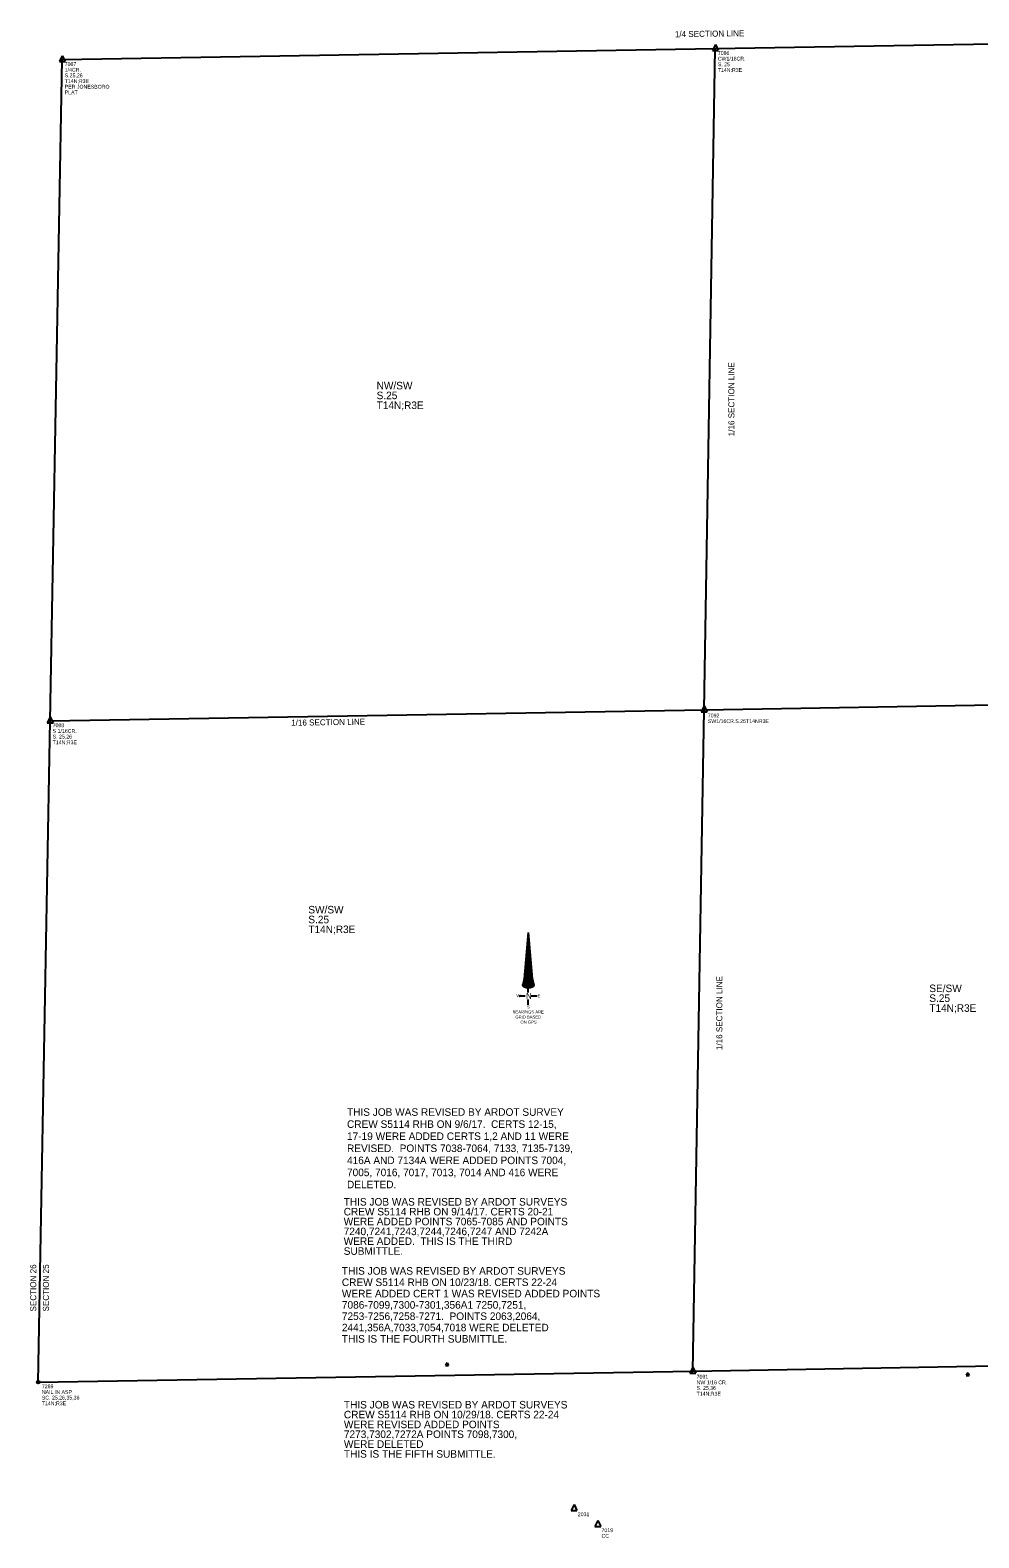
# Model space of a CAD drawing. Extents: x 1688544 to 1704497, y 535668 to 545444.
# Drawn here: x 1688544 to 1690431, y 538520 to 541517 of the extents above; entities that cross this region are included whole.
import ezdxf

# ---------------------------------------------------------------- set-up
doc = ezdxf.new("R2010")
doc.units = 0
for name, color, linetype in [('Default', 7, 'Continuous'), ('S_CAL_CORNER', 7, 'Continuous'), ('S_CAL_CORNER_ANNOT', 7, 'Continuous'), ('S_IRON_PIN', 7, 'Continuous'), ('S_IRON_PIN_ANNOT', 7, 'Continuous'), ('S_QSECTION', 7, 'Continuous'), ('S_SECONDARY_CTL', 7, 'Continuous'), ('S_SECTION', 7, 'Continuous'), ('S_SECTION_ANNOT', 7, 'Continuous'), ('S_SIXTEEN_SECTION', 7, 'Continuous'), ('S_TITLE_BLOCK', 7, 'Continuous')]:
    doc.layers.add(name, color=color, linetype=linetype)

msp = doc.modelspace()

# ---------------------------------------------------------------- linework, layer by layer
at = {"layer": 'S_CAL_CORNER'}
for p, q in [((1689906.9, 541488.4), (1689901, 541476.6)), ((1689906.9, 541488.4), (1689901, 541476.6)), ((1689906.9, 541488.4), (1689901, 541476.6)), ((1689906.9, 541488.4), (1689912.7, 541476.6)), ((1689906.9, 541488.4), (1689912.7, 541476.6)), ((1689906.9, 541488.4), (1689912.7, 541476.6)), ((1688607.6, 541466.4), (1688601.8, 541454.6)), ((1688607.6, 541466.4), (1688601.8, 541454.6)), ((1688607.6, 541466.4), (1688601.8, 541454.6)), ((1688601.8, 541454.6), (1688613.4, 541454.6)), ((1688601.8, 541454.6), (1688613.4, 541454.6)), ((1688601.8, 541454.6), (1688613.4, 541454.6)), ((1688607.6, 541466.4), (1688613.4, 541454.6)), ((1688607.6, 541466.4), (1688613.4, 541454.6)), ((1688607.6, 541466.4), (1688613.4, 541454.6)), ((1689901, 541476.6), (1689912.7, 541476.6)), ((1689901, 541476.6), (1689912.7, 541476.6)), ((1689901, 541476.6), (1689912.7, 541476.6)), ((1689884.5, 540174.1), (1689878.6, 540162.3)), ((1689884.5, 540174.1), (1689878.6, 540162.3)), ((1689884.5, 540174.1), (1689878.6, 540162.3)), ((1689878.6, 540162.3), (1689890.3, 540162.3)), ((1689878.6, 540162.3), (1689890.3, 540162.3)), ((1689878.6, 540162.3), (1689890.3, 540162.3)), ((1689884.5, 540174.1), (1689890.3, 540162.3)), ((1689884.5, 540174.1), (1689890.3, 540162.3)), ((1689884.5, 540174.1), (1689890.3, 540162.3)), ((1688583.6, 540152.1), (1688577.7, 540140.2)), ((1688583.6, 540152.1), (1688577.7, 540140.2)), ((1688583.6, 540152.1), (1688577.7, 540140.2)), ((1688577.7, 540140.2), (1688589.4, 540140.2)), ((1688577.7, 540140.2), (1688589.4, 540140.2)), ((1688577.7, 540140.2), (1688589.4, 540140.2)), ((1688583.6, 540152.1), (1688589.4, 540140.2)), ((1688583.6, 540152.1), (1688589.4, 540140.2)), ((1688583.6, 540152.1), (1688589.4, 540140.2)), ((1689862.1, 538859.8), (1689856.3, 538847.9)), ((1689862.1, 538859.8), (1689856.3, 538847.9)), ((1689862.1, 538859.8), (1689856.3, 538847.9)), ((1689856.3, 538847.9), (1689868, 538847.9)), ((1689856.3, 538847.9), (1689868, 538847.9)), ((1689856.3, 538847.9), (1689868, 538847.9)), ((1689862.1, 538859.8), (1689868, 538847.9)), ((1689862.1, 538859.8), (1689868, 538847.9)), ((1689862.1, 538859.8), (1689868, 538847.9)), ((1689625.8, 538586.2), (1689619.9, 538574.4)), ((1689619.9, 538574.4), (1689631.6, 538574.4)), ((1689625.8, 538586.2), (1689631.6, 538574.4)), ((1689673, 538554.6), (1689667.1, 538542.7)), ((1689667.1, 538542.7), (1689678.8, 538542.7)), ((1689673, 538554.6), (1689678.8, 538542.7))]:
    msp.add_line(p, q, dxfattribs=at)
at = {"layer": 'S_IRON_PIN'}
for radius in [2.91, 0.411, 0.262, 0.212, 0.0822, 0.145, 0.0581]:
    msp.add_circle((1688559.5, 538829.7), radius, dxfattribs=at)
at = {"layer": 'S_QSECTION'}
for p, q in [((1688607.5, 541458.5), (1689906.8, 541480.5)), ((1689906.8, 541480.5), (1691206, 541502.5))]:
    msp.add_line(p, q, dxfattribs=at)
at = {"layer": 'S_SECONDARY_CTL'}
for p, q in [((1689373.1, 538867.8), (1689370.1, 538862.8)), ((1689370.1, 538862.8), (1689376, 538862.8)), ((1689373.1, 538867.8), (1689376, 538862.8)), ((1690409, 538848.1), (1690406, 538843.1)), ((1690409, 538848.1), (1690406, 538843.1)), ((1690406, 538843.1), (1690412, 538843.1)), ((1690406, 538843.1), (1690412, 538843.1)), ((1690409, 538848.1), (1690412, 538843.1)), ((1690409, 538848.1), (1690412, 538843.1))]:
    msp.add_line(p, q, dxfattribs=at)
for centre, radius in [((1689373.1, 538865.1), 0.311), ((1689373.1, 538865.1), 0.183), ((1689373.1, 538865.1), 0.103), ((1690409, 538845.5), 0.311), ((1690409, 538845.5), 0.311), ((1690409, 538845.5), 0.183), ((1690409, 538845.5), 0.183), ((1690409, 538845.5), 0.103), ((1690409, 538845.5), 0.103)]:
    msp.add_circle(centre, radius, dxfattribs=at)
at = {"layer": 'S_SECTION'}
for p, q in [((1688583.5, 540144.1), (1688607.5, 541458.5)), ((1688559.5, 538829.7), (1688583.5, 540144.1)), ((1689862.1, 538851.8), (1691164.6, 538873.9)), ((1688559.5, 538829.7), (1689862.1, 538851.8))]:
    msp.add_line(p, q, dxfattribs=at)
at = {"layer": 'S_SIXTEEN_SECTION'}
for p, q in [((1689884.4, 540166.1), (1689906.8, 541480.5)), ((1688583.5, 540144.1), (1689884.4, 540166.1)), ((1689862.1, 538851.8), (1689884.4, 540166.1)), ((1689884.4, 540166.1), (1691185.3, 540188.2))]:
    msp.add_line(p, q, dxfattribs=at)
at = {"layer": 'S_TITLE_BLOCK'}
for p, q in [((1689534.7, 539723.5), (1689526.7, 539631.5)), ((1689533.6, 539711.4), (1689535.9, 539709.1)), ((1689533.8, 539713.3), (1689535.7, 539711.4)), ((1689534, 539715.3), (1689535.5, 539713.7)), ((1689534.1, 539717.2), (1689535.3, 539716.1)), ((1689534.3, 539719.2), (1689535.1, 539718.4)), ((1689534.5, 539721.2), (1689534.9, 539720.7)), ((1689534.6, 539723.1), (1689534.7, 539723)), ((1689534.7, 539723.5), (1689542.7, 539631.5)), ((1689531.1, 539682.1), (1689539, 539674.2)), ((1689531.2, 539684.1), (1689538.8, 539676.6)), ((1689531.4, 539686), (1689538.6, 539678.9)), ((1689531.6, 539688), (1689538.3, 539681.2)), ((1689531.8, 539689.9), (1689538.1, 539683.5)), ((1689531.9, 539691.9), (1689537.9, 539685.9)), ((1689532.1, 539693.8), (1689537.7, 539688.2)), ((1689532.3, 539695.8), (1689537.5, 539690.5)), ((1689532.4, 539697.7), (1689537.3, 539692.8)), ((1689532.6, 539699.7), (1689537.1, 539695.2)), ((1689532.8, 539701.6), (1689536.9, 539697.5)), ((1689532.9, 539703.6), (1689536.7, 539699.8)), ((1689533.1, 539705.5), (1689536.5, 539702.1)), ((1689533.3, 539707.5), (1689536.3, 539704.4)), ((1689533.5, 539709.4), (1689536.1, 539706.8)), ((1689528.5, 539652.8), (1689542, 539639.4)), ((1689528.7, 539654.8), (1689541.8, 539641.7)), ((1689528.9, 539656.7), (1689541.6, 539644)), ((1689529, 539658.7), (1689541.4, 539646.4)), ((1689529.2, 539660.7), (1689541.2, 539648.7)), ((1689529.4, 539662.6), (1689541, 539651)), ((1689529.6, 539664.6), (1689540.8, 539653.3)), ((1689529.7, 539666.5), (1689540.6, 539655.7)), ((1689529.9, 539668.5), (1689540.4, 539658)), ((1689530.1, 539670.4), (1689540.2, 539660.3)), ((1689530.2, 539672.4), (1689540, 539662.6)), ((1689530.4, 539674.3), (1689539.8, 539664.9)), ((1689530.6, 539676.3), (1689539.6, 539667.3)), ((1689530.7, 539678.2), (1689539.4, 539669.6)), ((1689530.9, 539680.2), (1689539.2, 539671.9)), ((1689526.7, 539631.5), (1689523.7, 539619)), ((1689524.6, 539622.8), (1689525.8, 539621.7)), ((1689525, 539624.5), (1689527.1, 539622.5)), ((1689525.4, 539626.2), (1689528.6, 539623.1)), ((1689525.8, 539628), (1689530.3, 539623.5)), ((1689526.3, 539629.7), (1689532.1, 539623.8)), ((1689526.7, 539631.4), (1689534.1, 539624)), ((1689526.8, 539633.3), (1689536.3, 539623.9)), ((1689527, 539635.3), (1689538.7, 539623.6)), ((1689527.2, 539637.2), (1689541.7, 539622.7)), ((1689527.3, 539639.2), (1689545, 539621.5)), ((1689527.5, 539641.1), (1689544.4, 539624.3)), ((1689527.7, 539643.1), (1689543.7, 539627.1)), ((1689527.9, 539645), (1689543.1, 539629.8)), ((1689528, 539647), (1689542.6, 539632.4)), ((1689528.2, 539648.9), (1689542.4, 539634.7)), ((1689528.4, 539650.9), (1689542.2, 539637.1)), ((1689542.7, 539631.5), (1689545.6, 539619)), ((1689516.7, 539597.5), (1689528.7, 539597.5)), ((1689523.8, 539619.4), (1689523.8, 539619.4)), ((1689524.2, 539621.1), (1689524.6, 539620.7)), ((1689534.7, 539604.5), (1689534.7, 539618.5)), ((1689540.7, 539597.5), (1689552.7, 539597.5)), ((1689534.7, 539579.5), (1689534.7, 539590.5))]:
    msp.add_line(p, q, dxfattribs=at)
for major_axis in [(11, 0), (9, 0), (7, 0), (5, 0), (3, 0), (1, 0)]:
    msp.add_ellipse((1689534.7, 539618.5), major_axis=major_axis, ratio=0.5, dxfattribs=at)

# ---------------------------------------------------------------- texts
at = {"layer": 'Default'}
for s, p in [('S.25', (1689233, 540783.6)), ('NW/SW', (1689233, 540803.1)), ('T14N;R3E', (1689233, 540764)), ('SW/SW', (1689097.1, 539761.4)), ('S.25', (1689097.1, 539741.8)), ('T14N;R3E', (1689097.1, 539722.3)), ('SE/SW', (1690332.5, 539605)), ('S.25', (1690332.5, 539585.4)), ('T14N;R3E', (1690332.5, 539565.8)), ('THIS JOB WAS REVISED BY ARDOT SURVEY ', (1689174.1, 539359.1)), ('CREW S5114 RHB ON 9/6/17.  CERTS 12-15,', (1689174.1, 539335.1)), ('17-19 WERE ADDED CERTS 1,2 AND 11 WERE', (1689174.1, 539311.1)), ('REVISED.  POINTS 7038-7064, 7133, 7135-7139,', (1689174.1, 539287.1)), ('416A AND 7134A WERE ADDED POINTS 7004, ', (1689174.1, 539263.1)), ('7005, 7016, 7017, 7013, 7014 AND 416 WERE', (1689174.1, 539239.1)), ('DELETED.  ', (1689174.1, 539215.1)), ('THIS JOB WAS REVISED BY ARDOT SURVEYS', (1689167.5, 539180.7)), ('CREW S5114 RHB ON 9/14/17. CERTS 20-21', (1689167.5, 539161.1)), ('WERE ADDED POINTS 7065-7085 AND POINTS', (1689167.5, 539141.5)), ('WERE ADDED.  THIS IS THE THIRD ', (1689167.5, 539102.4)), ('7240,7241,7243,7244,7246,7247 AND 7242A', (1689167.5, 539121.9)), ('SUBMITTLE.', (1689167.5, 539082.8)), ('THIS JOB WAS REVISED BY ARDOT SURVEYS', (1689163.9, 539043.3)), ('CREW S5114 RHB ON 10/23/18. CERTS 22-24', (1689163.9, 539020.8)), ('WERE ADDED CERT 1 WAS REVISED ADDED POINTS ', (1689163.9, 538998.3)), ('7086-7099,7300-7301,356A1 7250,7251,', (1689163.9, 538975.8)), ('7253-7256,7258-7271.  POINTS 2063,2064,', (1689163.9, 538953.3)), ('2441,356A,7033,7054,7018 WERE DELETED', (1689163.9, 538930.8)), ('THIS IS THE FOURTH SUBMITTLE.', (1689163.9, 538908.3)), ('THIS JOB WAS REVISED BY ARDOT SURVEYS', (1689167.9, 538777.4)), ('WERE REVISED ADDED POINTS ', (1689167.9, 538738.2)), ('CREW S5114 RHB ON 10/29/18. CERTS 22-24', (1689167.9, 538757.8)), ('7273,7302,7272A POINTS 7098,7300,', (1689167.9, 538718.7)), ('WERE DELETED', (1689167.9, 538699.1)), ('THIS IS THE FIFTH SUBMITTLE.', (1689167.9, 538679.5))]:
    msp.add_text(s, height=15, dxfattribs=at).set_placement(p)
at = {"layer": 'S_CAL_CORNER_ANNOT'}
for s, p in [('7087', (1688612.5, 541446)), ('S. 25', (1689911.8, 541445.5)), ('7086', (1689911.8, 541468)), ('CW1/16CR.', (1689911.8, 541456.7)), ('T14N;R3E', (1688612.5, 541412.2)), ('S.25,26', (1688612.5, 541423.5)), ('1/4CR.', (1688612.5, 541434.7)), ('T14N;R3E', (1689911.8, 541434.2)), ('PER JONESBORO', (1688612.5, 541401)), ('PLAT', (1688612.5, 541389.7)), ('7088', (1688588.5, 540131.6)), ('7092', (1689891.9, 540151.1)), ('SW1/16CR.S.25T14NR3E', (1689891.9, 540139.9)), ('T14N;R3E', (1688588.5, 540097.8)), ('S 1/16CR.', (1688588.5, 540120.3)), ('S. 25,26', (1688588.5, 540109.1)), ('7091', (1689869.6, 538836.8)), ('S. 25,36', (1689869.6, 538814.3)), ('NW 1/16 CR.', (1689869.6, 538825.5)), ('T14N;R3E', (1689869.6, 538803)), ('2031', (1689633.2, 538563.3)), ('7019', (1689680.4, 538531.6)), ('CC', (1689680.4, 538520.3))]:
    msp.add_text(s, height=7.5, dxfattribs=at).set_placement(p)
at = {"layer": 'S_IRON_PIN_ANNOT'}
for s, p in [('7269', (1688567, 538817.7)), ('NAIL IN ASP', (1688567, 538806.4)), ('T14N;R3E', (1688567, 538783.9)), ('SC. 25,26,35,36 ', (1688567, 538795.2))]:
    msp.add_text(s, height=7.5, dxfattribs=at).set_placement(p)
at = {"layer": 'S_SECONDARY_CTL'}
for p in [(1689371.9, 538863.1), (1690407.8, 538843.5), (1690407.8, 538843.5)]:
    msp.add_text('TV', height=1.5, dxfattribs=at).set_placement(p)
at = {"layer": 'S_SECTION_ANNOT'}
for s, rotation, p in [('1/4 SECTION LINE', 0.8773, (1689826.4, 541503)), ('1/16 SECTION LINE', 90, (1689944.8, 540709.9)), ('1/16 SECTION LINE', 0.8773, (1689063.1, 540134.4)), ('1/16 SECTION LINE', 90, (1689920.8, 539489.7)), ('SECTION 26', 90, (1688555.9, 538970.2)), ('SECTION 25', 90, (1688581.1, 538970.2))]:
    msp.add_text(s, height=12, rotation=rotation, dxfattribs=at).set_placement(p)
at = {"layer": 'S_TITLE_BLOCK'}
for s, height, p in [('W', 6, (1689511.1, 539594.5)), ('N', 12, (1689530.1, 539591.5)), ('E', 6, (1689553.1, 539594.5)), ('BEARINGS ARE', 6, (1689503.6, 539562.5)), ('S', 6, (1689532.3, 539572.5)), ('GRID BASED', 6, (1689509, 539552.5)), ('ON GPS', 6, (1689519.1, 539542.5))]:
    msp.add_text(s, height=height, rotation=359.9924, dxfattribs=at).set_placement(p)

doc.saveas('drawing.dxf')
